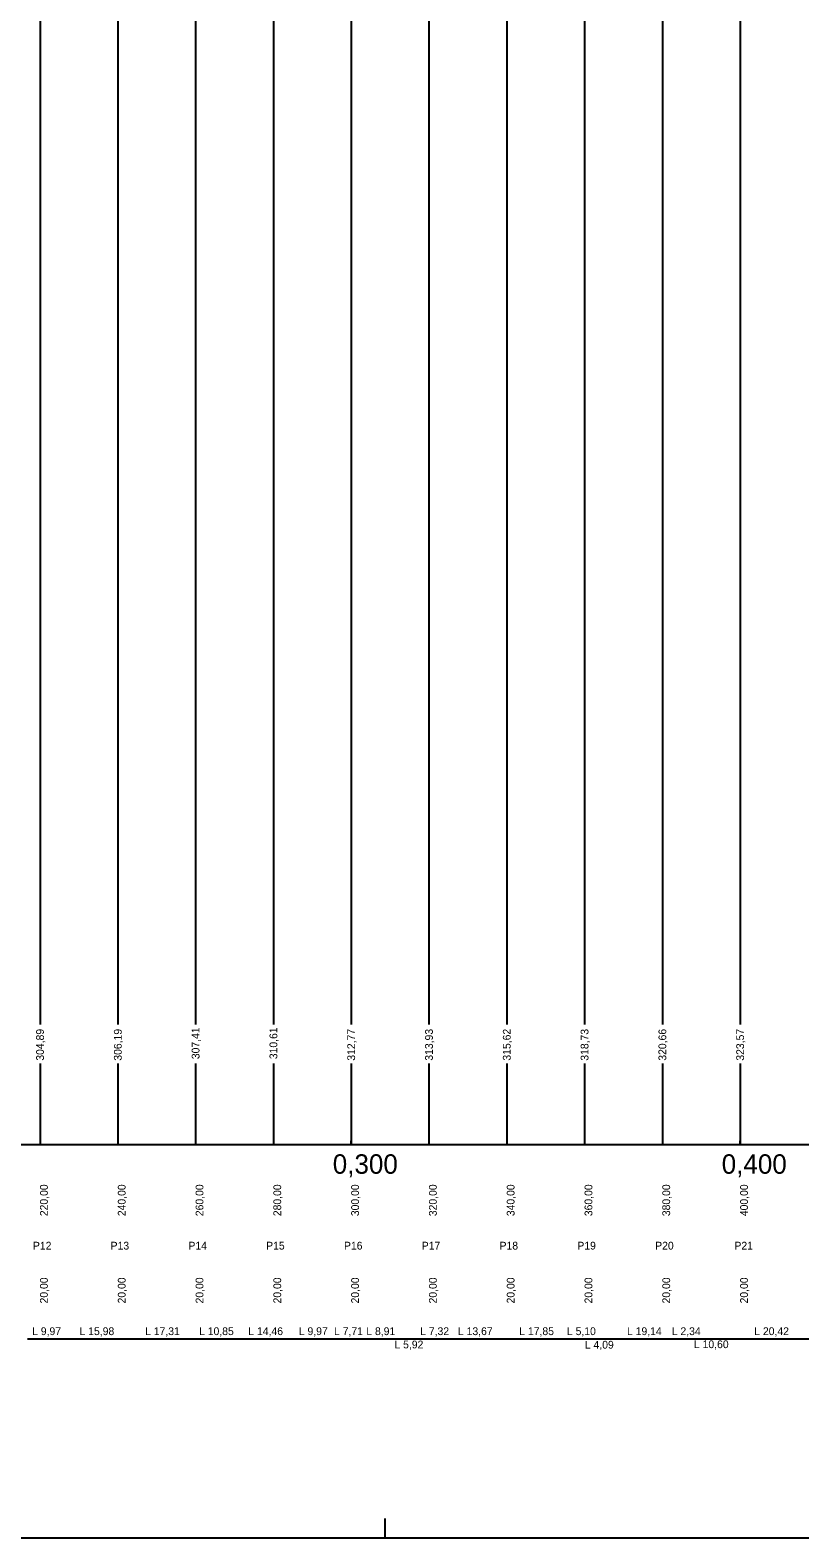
# Model space of a CAD drawing. Extents: x -500244 to -499404, y -1136557 to -1135632.
# Drawn here: x -499915 to -499717.1, y -1136556.6 to -1136168.8 of the extents above; entities that cross this region are included whole.
import ezdxf

# ---------------------------------------------------------------- set-up
doc = ezdxf.new("R2010")
doc.units = 0
for name, color, linetype in [('11', 7, 'Continuous'), ('13', 7, 'Continuous'), ('56', 7, 'Continuous'), ('hraniceABH', 7, 'Continuous')]:
    doc.layers.add(name, color=color, linetype=linetype)

msp = doc.modelspace()

# ---------------------------------------------------------------- linework, layer by layer
for points in [[(-499732.45, -1135969.69), (-499732.45, -1136385.42), (-499732.45, -1136395.42), (-499732.45, -1136424.49)], [(-499752.45, -1135998.82), (-499752.45, -1136385.42), (-499752.45, -1136395.42), (-499752.45, -1136424.49)], [(-499772.45, -1136018.17), (-499772.45, -1136385.42), (-499772.45, -1136395.42), (-499772.45, -1136424.49)], [(-499792.45, -1136049.23), (-499792.45, -1136385.42), (-499792.45, -1136395.42), (-499792.45, -1136424.49)], [(-499812.45, -1136066.14), (-499812.45, -1136385.42), (-499812.45, -1136395.42), (-499812.45, -1136424.49)], [(-499832.45, -1136077.69), (-499832.45, -1136385.42), (-499832.45, -1136395.42), (-499832.45, -1136424.49)], [(-499852.45, -1136099.28), (-499852.45, -1136385.42), (-499852.45, -1136395.42), (-499852.45, -1136424.49)], [(-499872.45, -1136131.36), (-499872.45, -1136385.42), (-499872.45, -1136395.42), (-499872.45, -1136424.49)], [(-499892.45, -1136143.55), (-499892.45, -1136385.42), (-499892.45, -1136395.42), (-499892.45, -1136424.49)], [(-499912.45, -1136156.48), (-499912.45, -1136385.42), (-499912.45, -1136395.42), (-499912.45, -1136424.49)], [(-499912.45, -1136434.55), (-499912.45, -1136455.42)], [(-499892.45, -1136434.55), (-499892.45, -1136455.42)], [(-499872.45, -1136434.55), (-499872.45, -1136455.42)], [(-499852.45, -1136434.55), (-499852.45, -1136455.42)], [(-499832.45, -1136434.55), (-499832.45, -1136455.42)], [(-499812.45, -1136434.55), (-499812.45, -1136455.42)], [(-499792.45, -1136434.55), (-499792.45, -1136455.42)], [(-499772.45, -1136434.55), (-499772.45, -1136455.42)], [(-499752.45, -1136434.55), (-499752.45, -1136455.42)], [(-499732.45, -1136434.55), (-499732.45, -1136455.42)], [(-499915.65, -1136505.42), (-499905.68, -1136505.42), (-499905.68, -1136505.42), (-499889.7, -1136505.42), (-499889.7, -1136505.42), (-499872.38, -1136505.42), (-499872.38, -1136505.42), (-499861.54, -1136505.42), (-499861.54, -1136505.42), (-499847.07, -1136505.42), (-499847.07, -1136505.42), (-499837.1, -1136505.42), (-499837.1, -1136505.42), (-499829.39, -1136505.42), (-499829.39, -1136505.42), (-499820.48, -1136505.42), (-499820.48, -1136505.42), (-499814.56, -1136505.42), (-499814.56, -1136505.42), (-499807.24, -1136505.42), (-499807.24, -1136505.42), (-499793.57, -1136505.42), (-499793.57, -1136505.42), (-499775.71, -1136505.42), (-499775.71, -1136505.42), (-499770.61, -1136505.42), (-499770.61, -1136505.42), (-499766.52, -1136505.42), (-499766.52, -1136505.42), (-499747.38, -1136505.42), (-499747.38, -1136505.42), (-499745.04, -1136505.42), (-499745.04, -1136505.42), (-499734.44, -1136505.42), (-499734.44, -1136505.42), (-499714.02, -1136505.42)]]:
    msp.add_lwpolyline(points)
at = {"layer": '56'}
for p, q in [((-499832.45, -1136455.42), (-499832.45, -1136454.42)), ((-499732.45, -1136455.42), (-499732.45, -1136454.42)), ((-500132.45, -1136455.42), (-499532.45, -1136455.42))]:
    msp.add_line(p, q, dxfattribs=at)
at = {"layer": 'hraniceABH'}
for p, q in [((-499823.68, -1136556.57), (-499823.68, -1136551.57)), ((-500243.68, -1136556.57), (-499403.68, -1136556.57))]:
    msp.add_line(p, q, dxfattribs=at)

# ---------------------------------------------------------------- texts
at = {"layer": '11'}
for s, p in [('304,89', (-499911.45, -1136433.84)), ('306,19', (-499891.45, -1136433.84)), ('307,41', (-499871.45, -1136433.45)), ('310,61', (-499851.45, -1136433.45)), ('312,77', (-499831.45, -1136433.84)), ('313,93', (-499811.45, -1136433.84)), ('315,62', (-499791.45, -1136433.82)), ('318,73', (-499771.45, -1136433.84)), ('320,66', (-499751.45, -1136433.84)), ('323,57', (-499731.45, -1136433.84)), ('220,00', (-499910.45, -1136473.83)), ('240,00', (-499890.45, -1136473.83)), ('260,00', (-499870.45, -1136473.83)), ('280,00', (-499850.45, -1136473.83)), ('300,00', (-499830.45, -1136473.83)), ('320,00', (-499810.45, -1136473.83)), ('340,00', (-499790.45, -1136473.83)), ('360,00', (-499770.45, -1136473.83)), ('380,00', (-499750.45, -1136473.83)), ('400,00', (-499730.45, -1136473.83)), ('20,00', (-499910.45, -1136496.28)), ('20,00', (-499890.45, -1136496.28)), ('20,00', (-499870.45, -1136496.28)), ('20,00', (-499850.45, -1136496.28)), ('20,00', (-499830.45, -1136496.28)), ('20,00', (-499810.45, -1136496.28)), ('20,00', (-499790.45, -1136496.28)), ('20,00', (-499770.45, -1136496.28)), ('20,00', (-499750.45, -1136496.28)), ('20,00', (-499730.45, -1136496.28))]:
    msp.add_text(s, height=2, rotation=90, dxfattribs=at).set_placement(p)
for s, p in [('P12', (-499914.27, -1136482.42)), ('P13', (-499894.3, -1136482.42)), ('P14', (-499874.29, -1136482.42)), ('P15', (-499854.31, -1136482.42)), ('P16', (-499834.3, -1136482.42)), ('P17', (-499814.3, -1136482.42)), ('P18', (-499794.3, -1136482.42)), ('P19', (-499774.3, -1136482.42)), ('P20', (-499754.29, -1136482.42)), ('P21', (-499733.91, -1136482.42)), ('L 9,97', (-499914.48, -1136504.42)), ('L 15,98', (-499902.29, -1136504.42)), ('L 17,31', (-499885.44, -1136504.42)), ('L 10,85', (-499871.56, -1136504.42)), ('L 14,46', (-499858.9, -1136504.42)), ('L 9,97', (-499845.91, -1136504.42)), ('L 7,71', (-499836.87, -1136504.42)), ('L 8,91', (-499828.56, -1136504.42)), ('L 7,32', (-499814.71, -1136504.42)), ('L 13,67', (-499805, -1136504.42)), ('L 17,85', (-499789.24, -1136504.42)), ('L 5,10', (-499776.98, -1136504.42)), ('L 19,14', (-499761.54, -1136504.42)), ('L 2,34', (-499750.03, -1136504.42)), ('L 20,42', (-499728.82, -1136504.42)), ('L 5,92', (-499821.33, -1136507.84)), ('L 4,09', (-499772.38, -1136507.9)), ('L 10,60', (-499744.33, -1136507.78))]:
    msp.add_text(s, height=2, dxfattribs=at).set_placement(p)
at = {"layer": '13'}
for s, p in [('0,300', (-499837.19, -1136462.92)), ('0,400', (-499737.19, -1136462.92))]:
    msp.add_text(s, height=5, dxfattribs=at).set_placement(p)

doc.saveas('drawing.dxf')
